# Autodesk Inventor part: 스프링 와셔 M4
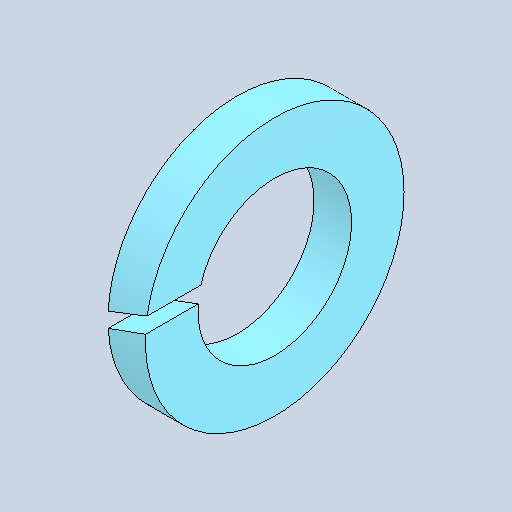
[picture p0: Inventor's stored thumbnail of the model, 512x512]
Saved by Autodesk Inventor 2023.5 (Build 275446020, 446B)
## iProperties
Created: 2026-07
Part Number: 스프링 와셔 M4
Material: 강철, 연강
Description: 스프링 잠금 와셔
Document SubType Name: Modeling
Designer: 1강의실14
Density: 7.85 g/cm^3
Appearance: 기본값
Author: jhkim
Sending System: Autodesk Inventor 2027
Preprocessor: ST-DEVELOPER v20.1
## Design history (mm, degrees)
node "스프링 와셔 M41"
node "솔리드1"
body "Solid1"
